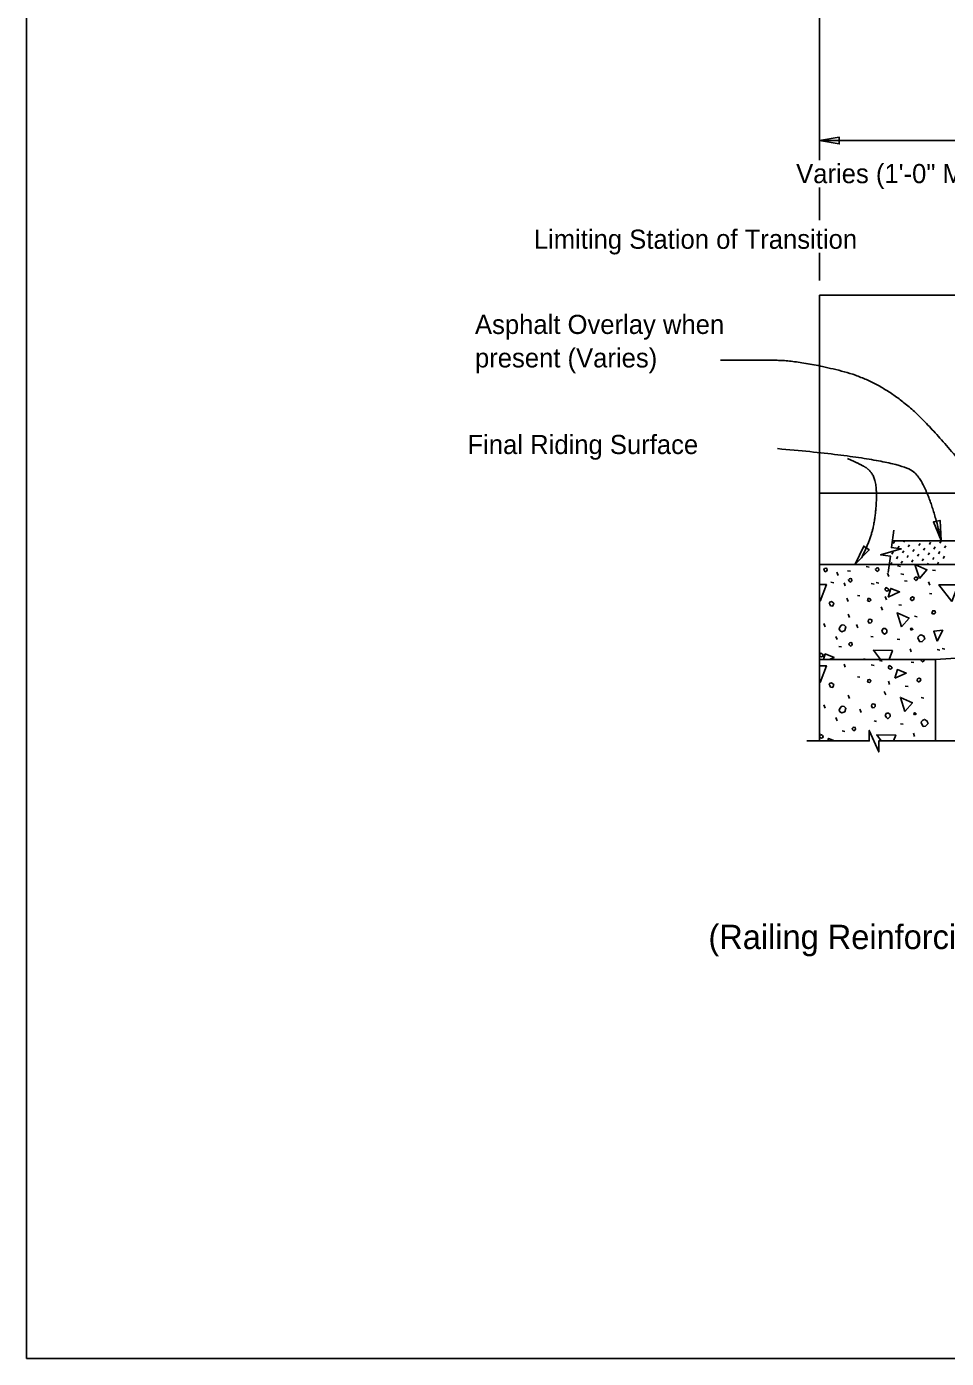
# Model space of a CAD drawing. Extents: x 0 to 41.1, y 0 to 25.9.
# Drawn here: x 0 to 9.68, y 0 to 14.01 of the extents above; entities that cross this region are included whole.
import ezdxf

# ---------------------------------------------------------------- set-up
doc = ezdxf.new("R2010")
doc.units = 0
for name, color, linetype in [('Dimension', 7, 'Continuous'), ('Miscellaneous', 7, 'Continuous'), ('Miscellaneous1', 7, 'Continuous'), ('TextStructures', 7, 'Continuous'), ('TrafBarrierConc', 7, 'Continuous')]:
    doc.layers.add(name, color=color, linetype=linetype)

msp = doc.modelspace()

# ---------------------------------------------------------------- linework, layer by layer
at = {"layer": 'Dimension'}
for p, q in [((8.341, 18.282), (8.341, 12.602)), ((11.841, 12.806), (8.341, 12.806)), ((8.341, 12.314), (8.341, 11.97)), ((8.341, 11.627), (8.341, 11.336))]:
    msp.add_line(p, q, dxfattribs=at)
for points in [[(0, 0), (41.051, 0), (41.051, 25.946), (0, 25.946)], [(8.341, 12.806), (8.549, 12.841), (8.549, 12.771)], [(9.622, 8.602), (9.61, 8.813), (9.541, 8.797)], [(8.717, 8.352), (8.866, 8.502), (8.808, 8.543)]]:
    msp.add_lwpolyline(points, close=True, dxfattribs=at)
for points in [[(9.064, 8.263), (9.088, 8.437), (8.985, 8.45), (9.094, 8.481), (9.202, 8.512), (9.099, 8.526), (9.124, 8.708)], [(10.581, 6.494), (8.965, 6.494), (8.965, 6.378), (8.866, 6.603), (8.866, 6.494), (8.21, 6.494)]]:
    msp.add_lwpolyline(points, dxfattribs=at)
for points in [[(7.301, 10.496), (7.628, 10.496), (8.127, 10.496), (9.025, 10.269), (9.778, 9.526), (10.477, 8.595)], [(7.901, 9.567), (9.185, 9.456), (9.489, 9.184), (9.622, 8.602)], [(8.635, 9.465), (8.759, 9.409), (8.875, 9.343), (8.941, 9.213), (8.941, 8.936), (8.886, 8.617), (8.784, 8.42)]]:
    msp.add_open_spline(points, degree=2, dxfattribs=at)
at = {"layer": 'Miscellaneous'}
for p, q in [((9.117, 8.57), (9.13, 8.592)), ((9.166, 8.521), (9.179, 8.543)), ((9.228, 8.583), (9.237, 8.599)), ((9.276, 8.534), (9.289, 8.556)), ((9.338, 8.596), (9.34, 8.599)), ((9.387, 8.547), (9.4, 8.569)), ((9.498, 8.56), (9.511, 8.582)), ((9.608, 8.573), (9.621, 8.595)), ((9.657, 8.524), (9.67, 8.546)), ((8.995, 8.449), (8.998, 8.454)), ((9.104, 8.459), (9.117, 8.481)), ((9.153, 8.41), (9.166, 8.433)), ((9.215, 8.472), (9.228, 8.494)), ((9.263, 8.423), (9.276, 8.445)), ((9.325, 8.485), (9.338, 8.507)), ((9.374, 8.436), (9.387, 8.458)), ((9.423, 8.387), (9.436, 8.41)), ((9.436, 8.498), (9.449, 8.52)), ((9.485, 8.449), (9.498, 8.471)), ((9.533, 8.4), (9.546, 8.423)), ((9.546, 8.511), (9.559, 8.533)), ((9.595, 8.462), (9.608, 8.484)), ((9.644, 8.413), (9.657, 8.436)), ((8.538, 8.233), (8.524, 8.268)), ((8.638, 8.282), (8.668, 8.277)), ((8.834, 8.326), (8.864, 8.321)), ((9.091, 8.349), (9.104, 8.371)), ((9.163, 8.334), (9.193, 8.329)), ((9.202, 8.361), (9.215, 8.384)), ((9.312, 8.374), (9.325, 8.397)), ((9.478, 8.349), (9.485, 8.361)), ((9.531, 8.29), (9.561, 8.285)), ((9.582, 8.351), (9.595, 8.374)), ((8.462, 8.162), (8.492, 8.157)), ((8.613, 8.123), (8.601, 8.157)), ((8.887, 8.15), (8.916, 8.143)), ((8.939, 8.159), (8.967, 8.152)), ((9.071, 8.221), (9.057, 8.256)), ((9.199, 8.25), (9.229, 8.245)), ((9.235, 8.178), (9.265, 8.173)), ((9.503, 8.133), (9.489, 8.168)), ((8.642, 7.96), (8.628, 7.996)), ((8.741, 8.024), (8.767, 8.019)), ((9.045, 7.978), (9.033, 8.011)), ((9.498, 8.045), (9.525, 8.04)), ((9.003, 7.868), (8.989, 7.904)), ((9.175, 7.923), (9.206, 7.92)), ((8.401, 7.692), (8.387, 7.727)), ((8.658, 7.793), (8.643, 7.828)), ((8.745, 7.681), (8.73, 7.716)), ((9.343, 7.805), (9.371, 7.798)), ((8.527, 7.559), (8.514, 7.593)), ((8.882, 7.592), (8.907, 7.589)), ((9.158, 7.564), (9.188, 7.559)), ((8.545, 7.488), (8.575, 7.483)), ((9.307, 7.43), (9.294, 7.463)), ((9.581, 7.456), (9.609, 7.449)), ((9.632, 7.466), (9.661, 7.458)), ((8.613, 7.268), (8.601, 7.302)), ((8.808, 7.356), (8.835, 7.35)), ((8.887, 7.295), (8.916, 7.288)), ((8.974, 7.339), (9.002, 7.332)), ((9.305, 7.323), (9.335, 7.318)), ((8.741, 7.169), (8.767, 7.164)), ((9.038, 6.979), (9.023, 7.014)), ((9.08, 7.088), (9.068, 7.122)), ((9.244, 7.069), (9.276, 7.065)), ((8.401, 6.837), (8.387, 6.872)), ((8.658, 6.938), (8.643, 6.973)), ((9.412, 6.95), (9.441, 6.943)), ((8.527, 6.705), (8.514, 6.738)), ((8.779, 6.791), (8.765, 6.826)), ((8.58, 6.598), (8.61, 6.593)), ((8.917, 6.703), (8.942, 6.699)), ((9.193, 6.674), (9.223, 6.669)), ((9.342, 6.54), (9.329, 6.574))]:
    msp.add_line(p, q, dxfattribs=at)
for points in [[(8.393, 8.283), (8.403, 8.272), (8.414, 8.279), (8.421, 8.29), (8.418, 8.307), (8.409, 8.309), (8.396, 8.307), (8.386, 8.297), (8.393, 8.283)], [(8.938, 8.287), (8.948, 8.276), (8.959, 8.283), (8.966, 8.294), (8.962, 8.311), (8.953, 8.313), (8.941, 8.311), (8.93, 8.301), (8.938, 8.287)], [(9.394, 8.202), (9.346, 8.349), (9.472, 8.294), (9.394, 8.202)], [(8.341, 8.138), (8.415, 8.137), (8.35, 7.962)], [(8.653, 8.174), (8.664, 8.164), (8.674, 8.171), (8.681, 8.181), (8.678, 8.199), (8.669, 8.201), (8.657, 8.199), (8.646, 8.188), (8.653, 8.174)], [(9.346, 8.19), (9.357, 8.18), (9.367, 8.187), (9.374, 8.197), (9.371, 8.215), (9.362, 8.217), (9.35, 8.215), (9.339, 8.204), (9.346, 8.19)], [(9.733, 7.959), (9.599, 8.136), (9.799, 8.134), (9.733, 7.959)], [(8.848, 7.966), (8.868, 7.961), (8.88, 7.969), (8.882, 7.982), (8.878, 7.985), (8.864, 7.992), (8.852, 7.991), (8.85, 7.978), (8.848, 7.966)], [(9.042, 8.071), (9.054, 8.069), (9.066, 8.074), (9.07, 8.085), (9.065, 8.094), (9.054, 8.101), (9.042, 8.106), (9.034, 8.092), (9.031, 8.081), (9.042, 8.071)], [(9.063, 8.006), (9.092, 8.098), (9.185, 8.061), (9.063, 8.006)], [(9.311, 7.971), (9.318, 7.971), (9.332, 7.978), (9.337, 7.994), (9.335, 8.003), (9.321, 8.01), (9.304, 7.999), (9.3, 7.989), (9.304, 7.978), (9.311, 7.971)], [(8.35, 7.962), (8.341, 7.974)], [(8.449, 7.93), (8.458, 7.915), (8.479, 7.911), (8.488, 7.927), (8.491, 7.941), (8.483, 7.95), (8.467, 7.959), (8.451, 7.953), (8.445, 7.938), (8.449, 7.93)], [(9.53, 7.83), (9.551, 7.83), (9.562, 7.84), (9.556, 7.86), (9.533, 7.862), (9.53, 7.851), (9.525, 7.842), (9.53, 7.83), (9.526, 7.833)], [(8.555, 7.655), (8.578, 7.642), (8.608, 7.655), (8.62, 7.692), (8.603, 7.709), (8.58, 7.715), (8.569, 7.708), (8.557, 7.688), (8.548, 7.672), (8.555, 7.655)], [(8.854, 7.748), (8.863, 7.732), (8.882, 7.734), (8.891, 7.746), (8.893, 7.766), (8.881, 7.771), (8.872, 7.773), (8.861, 7.769), (8.858, 7.766), (8.854, 7.748)], [(9.206, 7.693), (9.158, 7.84), (9.284, 7.785), (9.206, 7.693)], [(8.999, 7.649), (9.01, 7.628), (9.027, 7.617), (9.042, 7.628), (9.049, 7.638), (9.049, 7.66), (9.033, 7.675), (9.013, 7.674), (9.004, 7.665), (8.999, 7.649)], [(9.305, 7.658), (9.324, 7.667), (9.317, 7.674), (9.305, 7.679), (9.3, 7.667), (9.305, 7.658)], [(9.376, 7.573), (9.399, 7.536), (9.422, 7.538), (9.43, 7.546), (9.45, 7.566), (9.438, 7.596), (9.413, 7.61), (9.395, 7.603), (9.381, 7.589), (9.376, 7.573)], [(9.578, 7.542), (9.544, 7.646), (9.638, 7.658), (9.578, 7.542)], [(8.656, 7.5), (8.667, 7.49), (8.677, 7.497), (8.684, 7.508), (8.681, 7.525), (8.672, 7.527), (8.66, 7.525), (8.649, 7.515), (8.656, 7.5)], [(8.983, 7.349), (8.909, 7.446), (9.109, 7.444), (9.073, 7.349)], [(8.352, 7.381), (8.364, 7.379), (8.376, 7.384), (8.38, 7.395), (8.375, 7.404), (8.364, 7.411), (8.352, 7.416), (8.345, 7.402), (8.341, 7.391)], [(8.341, 7.391), (8.352, 7.381)], [(8.341, 7.283), (8.415, 7.283), (8.35, 7.108)], [(8.383, 7.349), (8.402, 7.409), (8.495, 7.371), (8.445, 7.349)], [(9.076, 7.251), (9.089, 7.249), (9.101, 7.254), (9.105, 7.265), (9.099, 7.274), (9.089, 7.281), (9.076, 7.286), (9.069, 7.272), (9.066, 7.261), (9.076, 7.251)], [(9.409, 7.349), (9.416, 7.336)], [(9.416, 7.336), (9.426, 7.325), (9.437, 7.332), (9.444, 7.343), (9.443, 7.349)], [(9.133, 7.152), (9.161, 7.244), (9.255, 7.207), (9.133, 7.152)], [(9.381, 7.116), (9.388, 7.116), (9.402, 7.123), (9.407, 7.139), (9.405, 7.148), (9.391, 7.155), (9.373, 7.145), (9.37, 7.134), (9.373, 7.123), (9.381, 7.116)], [(8.35, 7.108), (8.341, 7.119)], [(8.449, 7.076), (8.458, 7.06), (8.479, 7.056), (8.488, 7.072), (8.491, 7.086), (8.482, 7.095), (8.467, 7.104), (8.451, 7.099), (8.445, 7.083), (8.449, 7.076)], [(8.848, 7.111), (8.868, 7.106), (8.88, 7.115), (8.882, 7.127), (8.878, 7.131), (8.864, 7.138), (8.852, 7.136), (8.85, 7.123), (8.848, 7.111)], [(8.889, 6.858), (8.898, 6.842), (8.917, 6.844), (8.926, 6.857), (8.928, 6.876), (8.916, 6.881), (8.907, 6.883), (8.896, 6.88), (8.893, 6.876), (8.889, 6.858)], [(9.241, 6.804), (9.193, 6.95), (9.319, 6.895), (9.241, 6.804)], [(8.555, 6.8), (8.578, 6.788), (8.608, 6.8), (8.62, 6.837), (8.603, 6.855), (8.58, 6.86), (8.569, 6.853), (8.557, 6.834), (8.548, 6.818), (8.555, 6.8)], [(9.034, 6.759), (9.045, 6.738), (9.062, 6.727), (9.076, 6.738), (9.084, 6.749), (9.084, 6.77), (9.068, 6.786), (9.048, 6.784), (9.039, 6.775), (9.034, 6.759)], [(9.34, 6.768), (9.359, 6.777), (9.352, 6.784), (9.34, 6.789), (9.335, 6.777), (9.34, 6.768)], [(8.691, 6.611), (8.702, 6.6), (8.712, 6.607), (8.719, 6.618), (8.716, 6.636), (8.707, 6.637), (8.695, 6.636), (8.684, 6.625), (8.691, 6.611)], [(9.411, 6.683), (9.434, 6.646), (9.457, 6.648), (9.465, 6.657), (9.485, 6.676), (9.472, 6.706), (9.448, 6.72), (9.43, 6.713), (9.416, 6.699), (9.411, 6.683)], [(8.352, 6.526), (8.364, 6.524), (8.376, 6.529), (8.38, 6.54), (8.375, 6.549), (8.364, 6.556), (8.352, 6.561), (8.345, 6.547), (8.341, 6.537)], [(8.341, 6.537), (8.352, 6.526)], [(8.429, 6.494), (8.437, 6.519), (8.499, 6.494)], [(8.991, 6.494), (8.944, 6.556), (9.144, 6.554), (9.121, 6.494)]]:
    msp.add_lwpolyline(points, dxfattribs=at)
at = {"layer": 'Miscellaneous1'}
msp.add_lwpolyline([(0, 25.946), (41.051, 25.946), (41.051, 0), (0, 0)], close=True, dxfattribs=at)
at = {"layer": 'TrafBarrierConc'}
for p, q in [((18.365, 11.182), (8.341, 11.182)), ((8.341, 11.182), (8.341, 9.099)), ((8.341, 9.32), (8.341, 6.494)), ((18.365, 9.099), (8.341, 9.099)), ((9.109, 8.599), (11.378, 8.599)), ((8.341, 8.349), (20.055, 8.349)), ((9.561, 7.349), (13.561, 7.599)), ((9.561, 7.349), (8.341, 7.349)), ((9.561, 7.349), (9.561, 6.494))]:
    msp.add_line(p, q, dxfattribs=at)

# ---------------------------------------------------------------- texts
at = {"layer": 'Dimension'}
for s, height, p in [('Limiting Station of Transition', 0.2016, (5.336, 11.669)), ('Asphalt Overlay when ', 0.2016, (4.717, 10.773)), ('present (Varies)', 0.2016, (4.717, 10.421)), ('Final Riding Surface', 0.2016, (4.638, 9.51)), ('(Railing Reinforcing and Expansion Dowel Assemblies not shown for clarity)', 0.256, (7.173, 4.304))]:
    msp.add_text(s, height=height, dxfattribs=at).set_placement(p)
at = {"layer": 'TextStructures'}
msp.add_text('Varies (1\'-0" Min.)', height=0.2016, dxfattribs=at).set_placement((8.096, 12.359))

doc.saveas('drawing.dxf')
